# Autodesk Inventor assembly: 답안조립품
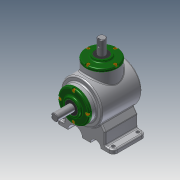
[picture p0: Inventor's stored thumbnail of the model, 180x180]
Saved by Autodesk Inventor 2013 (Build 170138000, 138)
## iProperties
Created: 2018-08
Part Number: 답안조립품
Document SubType Name: Assembly
Designer: Administrator
Author: Administrator
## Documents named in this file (14)
- C:\Users\Administrator\Desktop\480808V1007\답안조립품.iam
- C:\Users\Administrator\Desktop\480808V1007\본체.ipt
- C:\Users\Administrator\Desktop\480808V1007\메인 베벨기어.ipt
- C:\Users\Administrator\Desktop\480808V1007\메인 축.ipt
- 메인 축.ipt
- C:\Users\Administrator\Desktop\480808V1007\베어링 6203.ipt
- C:\Users\Administrator\Desktop\480808V1007\볼트 M4.ipt
- C:\Users\Administrator\Desktop\480808V1007\서브 베벨기어.ipt
- C:\Users\Administrator\Desktop\480808V1007\서브 축.ipt
- 서브 축.ipt
- C:\Users\Administrator\Desktop\480808V1007\오일실 17 32 8.ipt
- C:\Users\Administrator\Desktop\480808V1007\커버.ipt
- C:\Users\Administrator\Desktop\480808V1007\키 4x4.ipt
- C:\Users\Administrator\Desktop\480808V1007\키 5x5.ipt
